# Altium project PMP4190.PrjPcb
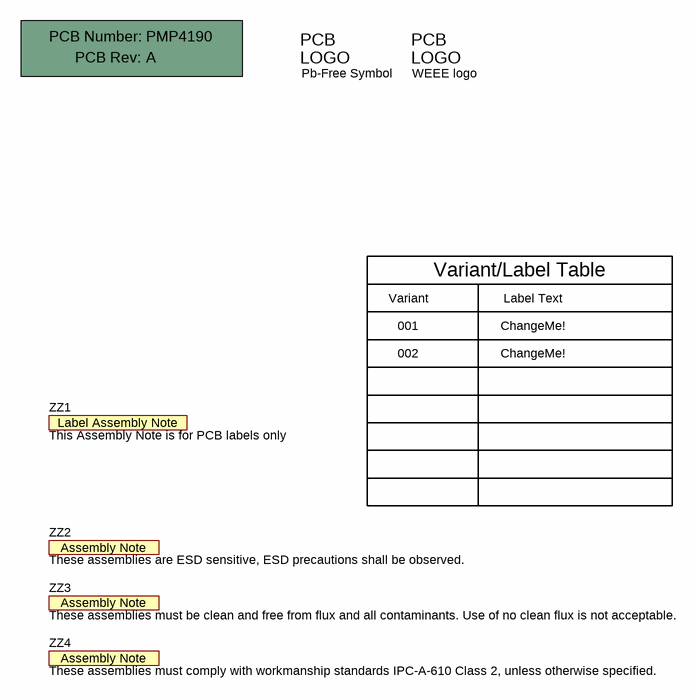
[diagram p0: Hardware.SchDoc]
TID: N/A; TechSupport: http://www.ti.com/support; SCH_Rev: B; PRJ_Title: 3V-6V Input, 5V/0.5A 1MHz Isolated Flyback; PRJ_Number: PMP4190; PRJ_Engineer: B King; PRJ_Customer: Public Release; PCB_Rev: A; PCB_Layout: Who did the Layout?; CopyrightYear: 2018
2 sheets, 43 parts. Net scope: global (net labels, ports and power ports of the same name join across sheets).
Board file: PMP4190_RevA.PcbDoc
Sheets:
  Hardware.SchDoc
  PMP4190_RevB.SchDoc

## Sheet Hardware.SchDoc
size 431 x 279 mm; Date: Not shown in title block; ApprovedBy: Not shown in title block; CheckedBy: Not shown in title block; Author: Not shown in title block; CompanyName: Not shown in title block; Engineer: Not shown in title block; Organization: Not shown in title block; Address1: Not shown in title block; Address2: Not shown in title block; Address3: Not shown in title block; Address4: Not shown in title block; DocumentNumber: 3; Revision: Use project parameter SCH_Rev; SheetNumber: 3; SheetTotal: 3; PageSetup: Record=PageOptions¦CenterHorizontal=True¦CenterVertical=True¦PrintScale=1.00¦XCorrection=1.00¦YCorrection=1.00¦PrintKind=0¦BorderSize=5000000¦LeftOffset=0¦BottomOffset=0¦Orientation=2¦PaperLength=1000¦PaperWidth=1000¦Scale=100¦PaperSource=15¦PrintQuality=600¦MediaType=1¦DitherType=10¦PaperKind=Letter¦PrintScaleMode=1

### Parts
!PCB  Printed Circuit Board  (value not drawn)  (mechanical)
Logo1  Pb-Free Symbol  [Pb-Free_Overlay_Medium]  (no BOM)
Logo2  WEEE logo  [WEEE_Minimum]  (no BOM)
ZZ1  This Assembly Note is for PCB labels only  [AssemblyNoteLabel]  (no BOM)
ZZ2  These assemblies are ESD sensitive, ESD precautions shall be observed.  [AssemblyNote]  (no BOM)
ZZ3  These assemblies must be clean and free from flux and all contaminants. Use of no clean flux is not acceptable.  [AssemblyNote]  (no BOM)
ZZ4  These assemblies must comply with workmanship standards IPC-A-610 Class 2, unless otherwise specified.  [AssemblyNote]  (no BOM)

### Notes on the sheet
- Variant
- Variant/Label Table
- Label Text
- 001
- 002
- ChangeMe!

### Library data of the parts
!PCB = CMP-0003618-2: Manufacturer: Any; PartNumber: PMP4190
Logo1 = CMP-0074839-1: SymbolCreator: a0412235
Logo2 = CMP-0074769-1
ZZ1 = CMP-0003616-3
ZZ2 = CMP-0077236-1
ZZ3 = CMP-0077237-1
ZZ4 = CMP-0077238-1

## Sheet PMP4190_RevB.SchDoc
size 431 x 279 mm; Date: Not shown in title block; ApprovedBy: Not shown in title block; CheckedBy: Not shown in title block; Author: Not shown in title block; CompanyName: Not shown in title block; Engineer: Not shown in title block; Organization: Not shown in title block; Address1: Not shown in title block; Address2: Not shown in title block; Address3: Not shown in title block; Address4: Not shown in title block; DocumentNumber: 2; Revision: Use project parameter SCH_Rev; SheetNumber: 2; SheetTotal: 3; PageSetup: Record=PageOptions¦CenterHorizontal=True¦CenterVertical=True¦PrintScale=1.00¦XCorrection=1.00¦YCorrection=1.00¦PrintKind=0¦BorderSize=5000000¦LeftOffset=0¦BottomOffset=0¦Orientation=2¦PaperLength=1000¦PaperWidth=1000¦Scale=100¦PaperSource=15¦PrintQuality=600¦MediaType=1¦DitherType=10¦PaperKind=Letter¦PrintScaleMode=1
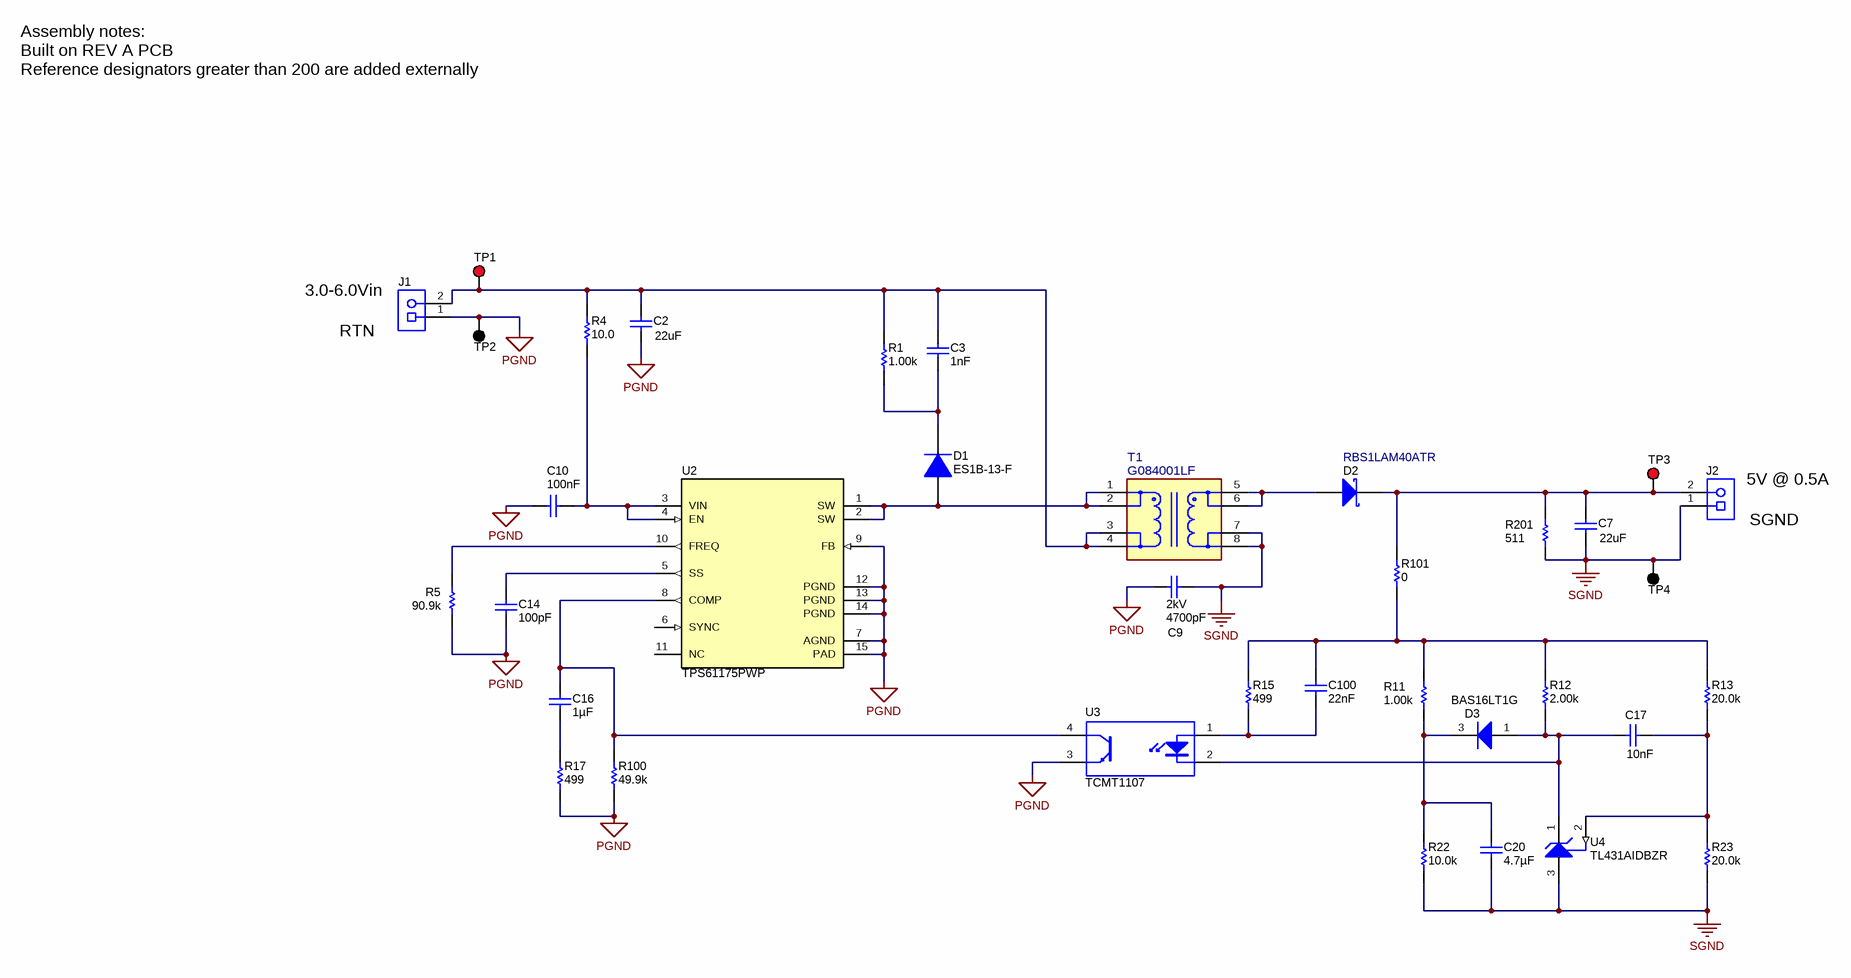
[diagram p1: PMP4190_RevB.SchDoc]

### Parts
C2  ValueDisplayed: 22uF  [1210_270]  (hidden comment: GRM32ER71A226ME20L)
C3  Cap_F: 1nF  [0603]  (hidden comment: C0603C102K5RACTU)
C7  ValueDisplayed: 22uF  [1210_270]  (hidden comment: GRM32ER71A226ME20L)
C9  VDC_V: 2kV  ValueDisplayed: 4700pF  [1812]  (hidden comment: 1812GC472KA1)
C10  Cap_F: 100nF  [0603]  (hidden comment: C1608X7R1H104K080AA)
C14  Cap_F: 100pF  [0603]  (hidden comment: CL10B101KB8NNNC)
C16  Cap_F: 1µF  [0603]  (hidden comment: CGJ3E1X7R1E105K080AC)
C17  Cap_F: 10nF  [0603]  (hidden comment: 885012206089)
C20  Cap_F: 4.7µF  [0805_HV]  (hidden comment: 885012207025)
C100  Cap_F: 22nF  [0603]  (hidden comment: C0603X223K5RACTU)
D1  ES1B-13-F  [SMA]
D2  RBS1LAM40ATR  [FP-RBS1LAM40ATR_SOD128-MFG]
D3  BAS16LT1G  [SOT-23]
J1  ED555/2DS  [TERM_BLK_ED555-2DS]  (value not drawn)
J2  ED555/2DS  [TERM_BLK_ED555-2DS]  (value not drawn)
R1  ValueDisplayed: 1.00k  [1206]  (hidden comment: RC1206FR-071KL)
R4  ValueDisplayed: 10.0  [0603]  (hidden comment: RC0603FR-0710RL)
R5  ValueDisplayed: 90.9k  [0603]  (hidden comment: RC0603FR-0790K9L)
R11  ValueDisplayed: 1.00k  [0603]  (hidden comment: RC0603FR-071KL)
R12  ValueDisplayed: 2.00k  [0603]  (hidden comment: RC0603FR-072KL)
R13  ValueDisplayed: 20.0k  [0603]  (hidden comment: RC0603FR-0720KL)
R15  ValueDisplayed: 499  [0603]  (hidden comment: RC0603FR-07499RL)
R17  ValueDisplayed: 499  [0603]  (hidden comment: RC0603FR-07499RL)
R22  ValueDisplayed: 10.0k  [0603]  (hidden comment: RC0603FR-0710KL)
R23  ValueDisplayed: 20.0k  [0603]  (hidden comment: RC0603FR-0720KL)
R100  ValueDisplayed: 49.9k  [0603]  (hidden comment: RC0603FR-0749K9L)
R101  ValueDisplayed: 0  [0603]  (hidden comment: RMCF0603ZT0R00)
R201  ValueDisplayed: 511  [0603]  (hidden comment: RC0603FR-07511RL)
T1  G084001LF  [FP-G084001LF_SMD8-MFG]
TP1  5000  [Keystone5000]  (value not drawn)
TP2  5001  [Keystone5001]  (value not drawn)
TP3  5000  [Keystone5000]  (value not drawn)
TP4  5001  [Keystone5001]  (value not drawn)
U2  TPS61175PWP  [PWP0014E_N]
U3  TCMT1107  [SOP-4]
U4  TL431AIDBZR  [DBZ0003A_N]

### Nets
PGND: C2.2 C9.2 C10.2 C14.2 J1.1 R5.1 R17.1 R100.1 TP2.1 U2.7(AGND) U2.9(FB) U2.12(PGND) U2.13(PGND) U2.14(PGND) U2.15(PAD) U3.3(E)
SGND: C7.2 C9.1 C20.2 J2.1 R22.1 R23.2 R201.1 T1.7 T1.8 TP4.1 U4.3(ANODE)
NetC2_1: C2.1 C3.1 J1.2 R1.2 R4.2 T1.3 T1.4 TP1.1
NetC3_2: C3.2 D1.1(K) R1.1
NetC7_1: C7.1 D2.1(K) J2.2 R101.2 R201.2 TP3.1
NetC10_1: C10.1 R4.1 U2.3(VIN) U2.4(EN)
NetC14_1: C14.1 U2.5(SS)
NetC16_1: C16.1 R100.2 U2.8(COMP) U3.4(C)
NetC16_2: C16.2 R17.2
NetC17_1: C17.1 D3.1(A) R12.1 U3.2(K) U4.1(CATHODE)
NetC17_2: C17.2 R13.1 R23.1 U4.2(REF)
NetC20_1: C20.1 D3.3(K) R11.1 R22.2
NetC100_1: C100.1 R11.2 R12.2 R13.2 R15.2 R101.1
NetC100_2: C100.2 R15.1 U3.1(A)
NetD1_2: D1.2(A) T1.1 T1.2 U2.1(SW) U2.2(SW)
NetD2_2: D2.2(A) T1.5 T1.6
NetR5_2: R5.2 U2.10(FREQ)

Not connected (* = marked no-connect by the designer): U2 6(SYNC) 11(NC)

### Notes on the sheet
- Assembly notes:                                                                                 Built on REV A PCB                                                                Reference designators greater than 200 are added externally
- (near J1) 3.0-6.0Vin
- RTN
- (near J2) SGND
- (near J2) 5V @ 0.5A

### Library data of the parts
C2 C7 = CMP-0009219-2: CAP, CERM, 22 uF, 10 V, +/- 10%, X7R, 1210; Manufacturer: MuRata; TaMin_C: -55°C; ESR_ohm: 2m; Polarized: N; SizeAreaWB_mm2: 14.7; Value1: 0.002 ohm; U/M: EA; Value: 22uF; TaMax_C: 125°C; SizeZ_mm: 2.7; SizeX_mm: 3.2; SizeY_mm: 2.5; Cap_Case: 1210; Value2: 10V; SizeArea_mm2: 8; Cap_F: 22µF; IRMS_A: 3.2A; AEC Category: Q200
C3 = CMP-0006847-4: CAP, CERM, 1000 pF, 50 V, +/- 10%, X7R, 0603; Manufacturer: Kemet; TaMin_C: -55°C; Polarized: N; SizeAreaWB_mm2: 4.68; Value1: Unknown; U/M: EA; Value: 1000pF; TaMax_C: 125°C; SizeZ_mm: 1; SizeX_mm: 1.6; SizeY_mm: 0.8; Value2: 50V; SizeArea_mm2: 1.28; AEC Category: Q200
C9 = CMP-0009294-2: CAP, CERM, 4700 pF, 2000 V, +/- 10%, X7R, 1812; Manufacturer: AVX; TaMin_C: -55°C; Polarized: N; SizeAreaWB_mm2: 23.1; Value1: Unknown; U/M: EA; Value: 4700pF; TaMax_C: 125°C; SizeZ_mm: 1.35; SizeX_mm: 4.5; SizeY_mm: 3.2; Value2: 2000V; SizeArea_mm2: 14.4; Cap_F: 4.7nF; AEC Category: Q200
C10 = CMP-0007044-5: CAP, CERM, 0.1 uF, 50 V, +/- 10%, X7R, 0603; Manufacturer: TDK; TaMin_C: -55°C; ESR_ohm: 0.0296; Polarized: N; SizeAreaWB_mm2: 4.68; Value1: 0.0296 ohm; U/M: EA; Value: 0.1uF; TaMax_C: 125°C; SizeZ_mm: 1; SizeX_mm: 1.6; SizeY_mm: 0.8; Value2: 50V; SizeArea_mm2: 1.28; IRMS_A: 971.99mA; AEC Category: Q200
C14 = CMP-0083857-1: CAP, CERM, 100 pF, 50 V,+/- 10%, X7R, 0603; Manufacturer: Samsung Electro-Mechanics; TaMin_C: -55°C; Polarized: N; SizeAreaWB_mm2: 4.68; U/M: EA; Value: 100pF; TaMax_C: 125°C; SizeZ_mm: 1; SizeX_mm: 1.6; SizeY_mm: 0.8; Value2: 50V; SizeArea_mm2: 1.28; AEC Category: Q200
C16 = CMP-0083856-1: CAP, CERM, 1 µF, 25 V,+/- 10%, X7R, 0603; Manufacturer: TDK; TaMin_C: -55°C; Polarized: N; SizeAreaWB_mm2: 4.68; U/M: EA; Value: 1uF; TaMax_C: 125°C; SizeZ_mm: 1; SizeX_mm: 1.6; SizeY_mm: 0.8; Value2: 25V; SizeArea_mm2: 1.28; AEC Category: Q200
C17 = CMP-0750039-1: CAP, CERM, 0.01 µF, 50 V,+/- 10%, X7R, 0603; Manufacturer: Wurth Elektronik; Polarized: N; AEC Category: Q200; TaMax_C: 125°C; SizeAreaWB_mm2: 4.68; Value: 0.01uF; SizeArea_mm2: 1.28; SizeY_mm: 0.8; SizeZ_mm: 1; ValueDisplayed: 0.01µF; SizeX_mm: 1.6; VDC_V: 50V; U/M: EA; TaMin_C: -55°C
C20 = CMP-0007690-2: CAP, CERM, 4.7 uF, 10 V, +/- 10%, X7R, 0805; Manufacturer: Wurth Elektronik; TaMin_C: -55°C; Polarized: N; SizeAreaWB_mm2: 6.75; Value1: Unknown; U/M: EA; Value: 4.7uF; TaMax_C: 125°C; SizeZ_mm: 1.45; SizeX_mm: 2; SizeY_mm: 1.25; Cap_Case: 0805; Value2: 10V; SizeArea_mm2: 2.5; AEC Category: Q200
C100 = CMP-0006984-4: CAP, CERM, 0.022 uF, 50 V, +/- 10%, X7R, 0603; Manufacturer: Kemet; TaMin_C: -55°C; Polarized: N; SizeAreaWB_mm2: 4.68; Value1: Unknown; U/M: EA; TaMax_C: 125°C; SizeZ_mm: 1; SizeX_mm: 1.6; SizeY_mm: 0.8; Value2: 50V; SizeArea_mm2: 1.28; AEC Category: Q200
D1 = CMP-0029022-2: Diode, Superfast Rectifier, 100 V, 1 A, SMA; Manufacturer: Diodes Inc.; Io_A: 1A; TJmax_C: 150°C; Value: 100V; Vf_V: 920mV; RJC_CperW: 25; SizeZ_mm: 2.87; SizeX_mm: 5.59; AEC Category: Q101; Value2: 0.92V; SizeArea_mm2: 16.3228; Green_REACh: Incomplete; SizeY_mm: 2.92; SizeAreaWB_mm2: 37.3428; Green_Lifecycle: Not Set
D2 = CMP-0088101-2: DIODE SCHOTTKY 20V 1A PMDTM; Manufacturer: Rohm; SizeZ_mm: 1.05mm; TJmax_C: 125°C; Symbol Name: SYM-RBS1LAM40ATR; AEC Category: Q101; AEC Qualified: No
D3 = CMP-0029193-2: Diode, Switching, 100 V, 0.2 A, SOT-23; Manufacturer: ON Semiconductor; Value: 100V; Green_Lifecycle: Active; SizeAreaWB_mm2: 14; Vf_V: 1.25V; SizeZ_mm: 1.1; AEC Qualified: N; SizeX_mm: 2.5; Green_REACh: Passed; AEC Category: Q101; Value1: 0.2A; SizeY_mm: 3; SizeArea_mm2: 7.5; Io_A: 200mA; TJmax_C: 150°C
J1 J2 = CMP-0074913-1: Terminal Block, 3.5mm Pitch, 2x1, TH; Manufacturer: On-Shore Technology; Cert_VDE: Y; CNHeader: False; Current_A: 6A; Green_Lifecycle: Active; Shrouded: N; Gender: Female; Green_REACh: Passed; Voltage_V: 150V; Row_Count: 1; Pitch_mm: 3.5; ContactFinish: Brass; CT: True
R1 = CMP-0017995-2: RES, 1.00 k, 1%, 0.25 W, 1206; Manufacturer: Yageo America; Power_W: 250mW; TempCo: 100 ppm/C; Value_Code: 1k00; U/M: EA; Value: 1.00k; EIA_Code: E96; Res_ohm: 1k; SizeX_mm: 3.2; SizeY_mm: 1.6; SizeZ_mm: 1.35; Value2: 0.25W; SizeArea_mm2: 5.12; VDC_V: 200V; AEC Category: Q200
R4 = CMP-0022751-4: RES, 10.0, 1%, 0.1 W, 0603; Manufacturer: Yageo; Power_W: 100mW; TempCo: 100 ppm/C; Value_Code: 10R0; Value: 10.0; EIA_Code: E96; Res_ohm: 10; SizeX_mm: 1.6; SizeY_mm: 0.8; SizeZ_mm: 1; Value2: 0.1W; SizeArea_mm2: 1.28; AEC Qualified: N; VDC_V: 75V; AEC Category: Q200; SizeAreaWB_mm2: 4.68
R5 = CMP-0023314-5: RES, 90.9 k, 1%, 0.1 W, 0603; Manufacturer: Yageo; Power_W: 100mW; TempCo: 100 ppm/C; Value_Code: 90k9; Value: 90.9k; EIA_Code: E96; SizeX_mm: 1.6; SizeY_mm: 0.8; SizeZ_mm: 1; Value2: 0.1W; SizeArea_mm2: 1.28; AEC Qualified: N; VDC_V: 75V; AEC Category: Q200; SizeAreaWB_mm2: 4.68
R11 = CMP-0022895-5: RES, 1.00 k, 1%, 0.1 W, 0603; Manufacturer: Yageo; Power_W: 100mW; TempCo: 100 ppm/C; Value_Code: 1k00; Value: 1.00k; EIA_Code: E96; Res_ohm: 1k; SizeX_mm: 1.6; SizeY_mm: 0.8; SizeZ_mm: 1; Value2: 0.1W; SizeArea_mm2: 1.28; AEC Qualified: N; VDC_V: 75V; AEC Category: Q200; SizeAreaWB_mm2: 4.68
R12 = CMP-0023000-5: RES, 2.00 k, 1%, 0.1 W, 0603; Manufacturer: Yageo; Power_W: 100mW; TempCo: 100 ppm/C; Value_Code: 2k00; Value: 2.00k; EIA_Code: E96; Res_ohm: 2k; SizeX_mm: 1.6; SizeY_mm: 0.8; SizeZ_mm: 1; Value2: 0.1W; SizeArea_mm2: 1.28; AEC Qualified: N; VDC_V: 75V; AEC Category: Q200; SizeAreaWB_mm2: 4.68
R13 R23 = CMP-0022906-5: RES, 20.0 k, 1%, 0.1 W, 0603; Manufacturer: Yageo; Power_W: 100mW; TempCo: 100 ppm/C; Value_Code: 20k0; Value: 20.0k; EIA_Code: E96; Res_ohm: 20k; SizeX_mm: 1.6; SizeY_mm: 0.8; SizeZ_mm: 1; Value2: 0.1W; SizeArea_mm2: 1.28; AEC Qualified: N; VDC_V: 75V; AEC Category: Q200; SizeAreaWB_mm2: 4.68
R15 R17 = CMP-0023141-5: RES, 499, 1%, 0.1 W, 0603; Manufacturer: Yageo; Power_W: 100mW; TempCo: 100 ppm/C; Value_Code: 499R; Value: 499; EIA_Code: E96; SizeX_mm: 1.6; SizeY_mm: 0.8; SizeZ_mm: 1; Value2: 0.1W; SizeArea_mm2: 1.28; AEC Qualified: N; VDC_V: 75V; AEC Category: Q200; SizeAreaWB_mm2: 4.68
R22 = CMP-0022746-5: RES, 10.0 k, 1%, 0.1 W, 0603; Manufacturer: Yageo; Power_W: 100mW; TempCo: 100 ppm/C; Value_Code: 10k0; Value: 10.0k; EIA_Code: E96; Res_ohm: 10k; SizeX_mm: 1.6; SizeY_mm: 0.8; SizeZ_mm: 1; Value2: 0.1W; SizeArea_mm2: 1.28; AEC Qualified: N; VDC_V: 75V; AEC Category: Q200; SizeAreaWB_mm2: 4.68
R100 = CMP-0023142-5: RES, 49.9 k, 1%, 0.1 W, 0603; Manufacturer: Yageo; Power_W: 100mW; TempCo: 100 ppm/C; Value_Code: 49k9; Value: 49.9k; EIA_Code: E96; SizeX_mm: 1.6; SizeY_mm: 0.8; SizeZ_mm: 1; Value2: 0.1W; SizeArea_mm2: 1.28; AEC Qualified: N; VDC_V: 75V; AEC Category: Q200; SizeAreaWB_mm2: 4.68
R101 = CMP-0023343-3: RES, 0, 1%, 0.1 W, AEC-Q200 Grade 0, 0603; Manufacturer: Stackpole Electronics Inc; Power_W: 100mW; TempCo: ppm/C; U/M: EA; Value: 0; SizeX_mm: 1.6; SizeY_mm: 0.8; SizeZ_mm: 1; Value2: 0.1W; SizeArea_mm2: 1.28; AEC Qualified: Y; AEC Category: Q200
R201 = CMP-0023165-5: RES, 511, 1%, 0.1 W, 0603; Manufacturer: Yageo; Power_W: 100mW; TempCo: 100 ppm/C; Value_Code: 511R; Value: 511; EIA_Code: E96; SizeX_mm: 1.6; SizeY_mm: 0.8; SizeZ_mm: 1; Value2: 0.1W; SizeArea_mm2: 1.28; AEC Qualified: N; VDC_V: 75V; AEC Category: Q200; SizeAreaWB_mm2: 4.68
T1 = CMP-0087741-1: FLYBACK TRANSFORMER; Manufacturer: GCI Technologies; SizeZ_mm: 9.5mm; Ind_H: 1µH; AEC Qualified: No; Ns1toNp: 1:2.5; Rsec1_ohm: 0.024; DCR_ohm: 5m
TP1 TP3 = CMP-0055137-1: Test Point, Miniature, Red, TH; Manufacturer: Keystone; CNHeader: FALSE; Green_Lifecycle: Active; Green_REACh: Passed; ContactFinish: Silver; CT: TRUE
TP2 TP4 = CMP-0055138-1: Test Point, Miniature, Black, TH; Manufacturer: Keystone; CNHeader: FALSE; Green_Lifecycle: Active; Green_REACh: Passed; ContactFinish: Silver; CT: TRUE
U2 = CMP-0067201-2: 3-A High Voltage Boost Converter with Soft-start and Programmable Switching Frequency, PWP0014E (TSSOP-14); Manufacturer: Texas Instruments; SizeX_mm: 6.4; SizeY_mm: 5.0; CompType: IC; SizeZ_mm: 1.2; SizeArea_mm2: 32.0; SizeAreaWB_mm2: 58.8; U/M: EA; Green_Lifecycle: Active; Green_REACh: Passed
U3 = CMP-0006166-3: Optocoupler, 3.75 kV, 80-160% CTR, SMT; Manufacturer: Vishay-Semiconductor; CTR (Max): 160%; SizeAreaWB_mm2: 43.65; CTR (Min): 80%; SizeZ_mm: 2.3; SizeX_mm: 7; SizeY_mm: 2.85; SizeArea_mm2: 19.95; Voltage_Isolation_Vrms: 3.75kV
U4 = CMP-0033090-1: Adjustable Precision Shunt Regulator, 34 ppm / degC, 100 mA, -40 to 85 degC, 3-pin SOT-23 (DBZ), Green (RoHS & no Sb/Br); Manufacturer: Texas Instruments; Iout/Iz(Max)(mA): 100; VO Adj(Max)(V): 36; Min Iz for Regulation(uA): 600; Temp Coeff(Typ)(ppm/ degree C): 34; Initial Accuracy @ 25/deg C(%): 1; SubFamily: Shunt Voltage Reference; Rating: Catalog; VO Adj(Min)(V): 2.495; Temp Coeff(Max)(ppm/ degree C): 92

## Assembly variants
001: not fitted FID1 FID2 FID3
